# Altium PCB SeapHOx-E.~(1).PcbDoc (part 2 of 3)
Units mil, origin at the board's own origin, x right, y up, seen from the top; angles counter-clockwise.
Board outline 7300 x 3625 mil, 4 copper layers (Top Layer, Internal Plane 1, Signal Layer 1, Bottom Layer), stack 30.634 mil thick; 244 components, 217 nets, 966 pads, 416 vias.
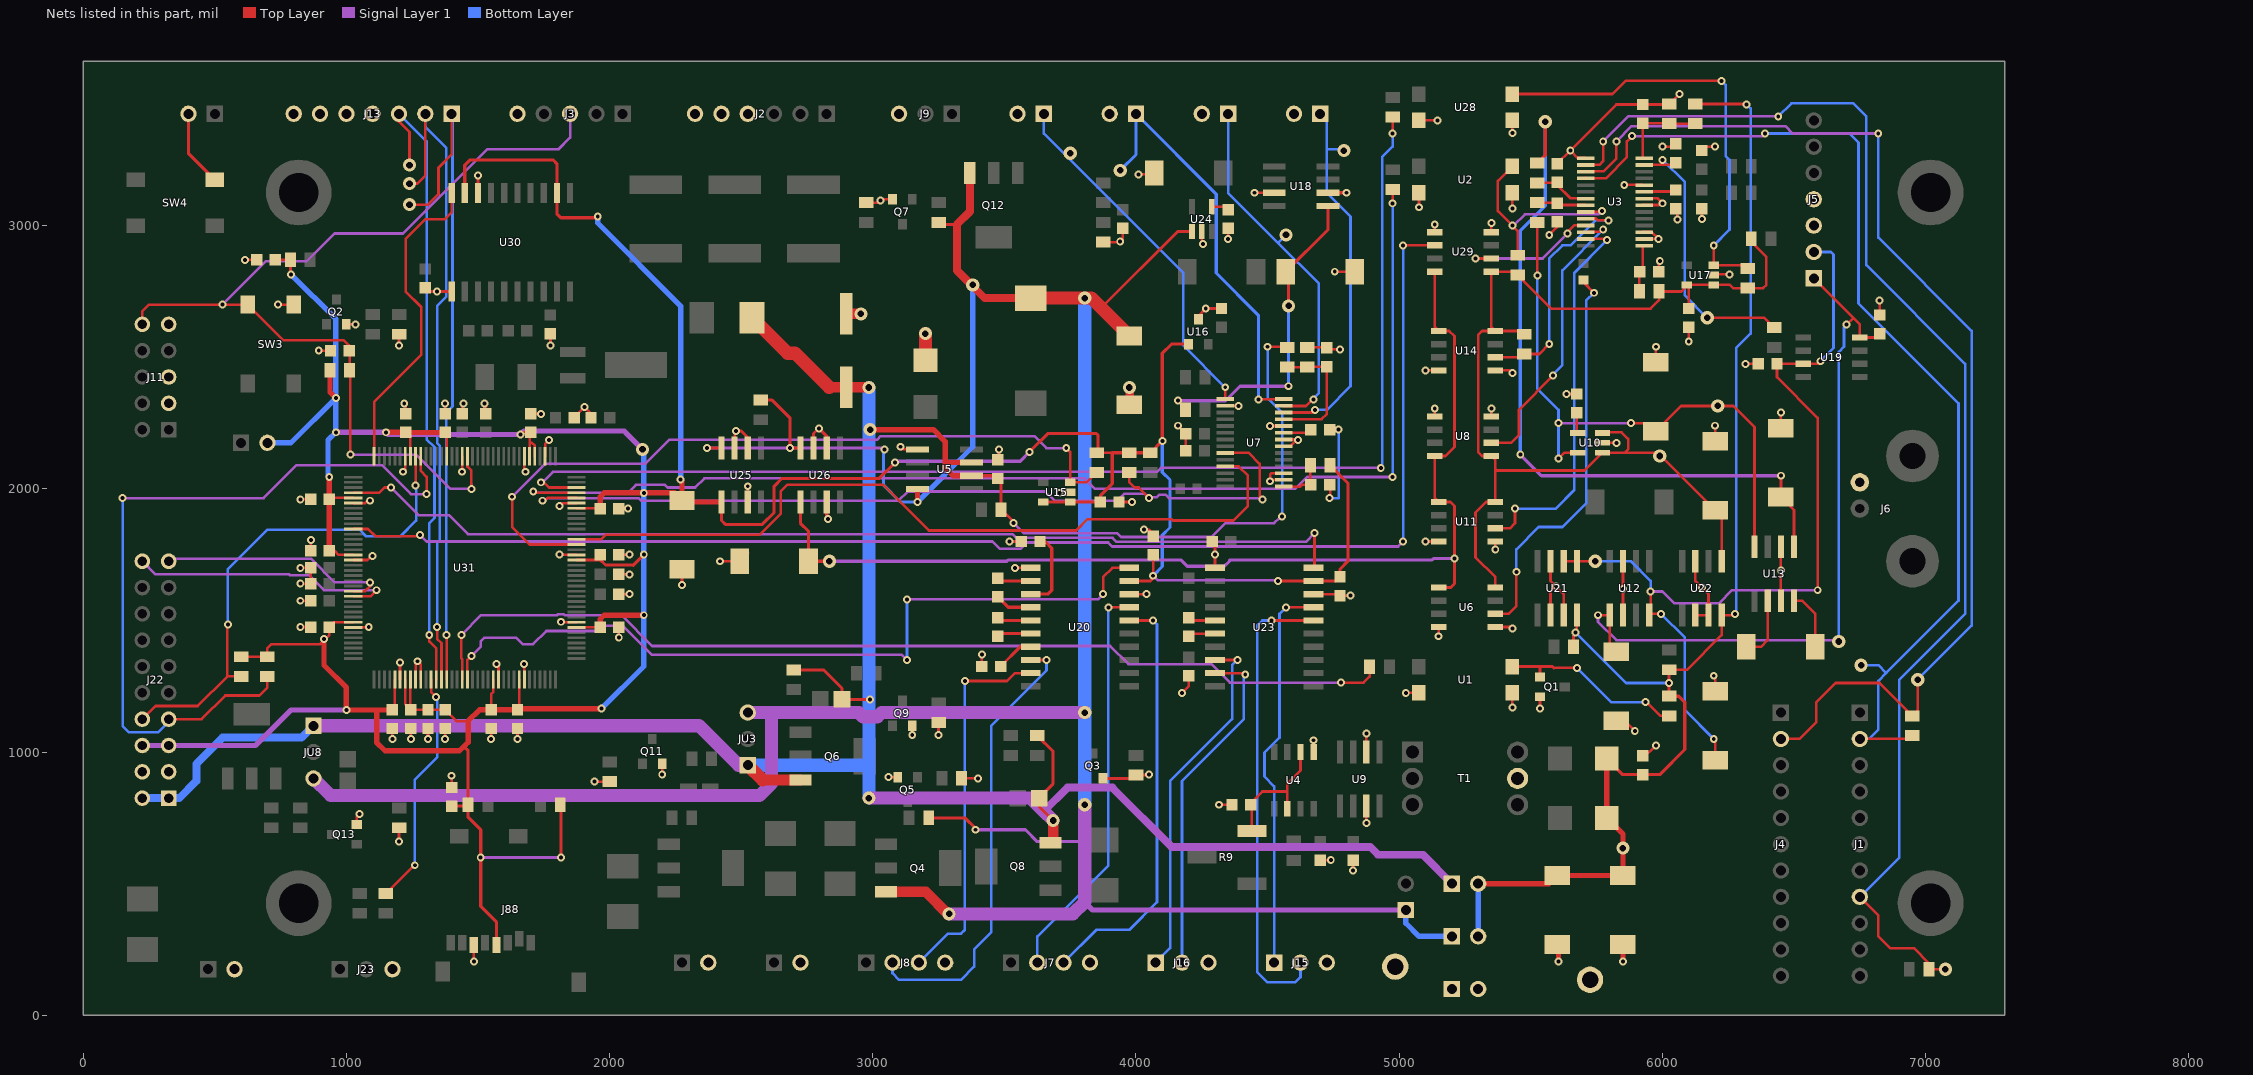
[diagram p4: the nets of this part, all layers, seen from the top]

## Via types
v1: diameter 30, hole 15, Top Layer to Bottom Layer, 378 vias
v2: diameter 50, hole 25, Top Layer to Bottom Layer, 38 vias

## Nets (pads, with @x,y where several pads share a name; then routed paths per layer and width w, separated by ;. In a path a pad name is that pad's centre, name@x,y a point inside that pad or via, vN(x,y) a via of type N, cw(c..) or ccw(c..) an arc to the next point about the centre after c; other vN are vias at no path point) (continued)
+3.3V: C7.1 C8.1 C9.1 C14.1 C22.1 C24.1 C44.2 C45.1 C50.2 C51.1 C74.2 C75.2 C76.2 C102.1 C112.1 C113.1 C114.2 C115.1 C116.1 C117.1 C118.1 J22.5 J22.6 J88.4 JU7.2 R45.2 R46.2 R47.2 R48.2 R49.2 R51.2 R57.1 R58.2 R62.2 R63.2 U15.1 U15.5 U16.1 U20.19 U23.19 U25.1 U30.12 U30.19 U31.5 U31.7 U31.8 U31.24 U31.29 U31.43 U31.56 U31.66 U31.77 U31.78 U31.94 U31.101 U31.113 U31.124 U31.137 | length 17978.5
  Top Layer w10: R63.2@600,1362.4 R62.2@700,1362.4 700,1395 715,1410 900,1410 915,1425 935.43,1445.43 C14.1@935.43,1475 953.74,1493.31 U31.137@1025.76,1493.31 ; C102.1@730.43,2870 R57.1@787.6,2870 787.6,2817.4 v1(790,2815) ; C7.1@935.43,1765 955,1765 970.79,1749.21 U31.124@1025.76,1749.21 ; C118.1@941.18,1965.75 U31.113@1025.76,1965.75 ; 1115,1037 1115,1040 ; 1147,1005 1150,1005 ; C74.2@1175,1160.43 1184.25,1169.68 U31.5@1184.25,1275.76 ; U31.7@1223.62,1275.76 1223.62,1181.81 C8.1@1243.31,1162.13 ; C117.1@1225,2214.57 1243.31,2196.26 U31.101@1243.31,2124.24 ; U31.8@1243.31,1275.76 C8.1@1243.31,1162.13 ; C116.1@1375,2214.57 1381.1,2208.46 U31.94@1381.1,2124.24 ; R51.2@1457.16,794.57 1462.6,794.57 R51.2@1462.6,800 ; 1462.6,1117.6 1417.83,1117.6 C9.1@1375,1160.43 C8.1@1245,1160.43 C8.1@1243.31,1162.13 ; C75.2@1550,1160.43 1550,1220 1558.27,1228.27 U31.24@1558.27,1275.76 ; C76.2@1650,1160.43 1650,1167.13 1656.69,1167.13 U31.29@1656.69,1275.76 ; v1(1662,2207) 1669.57,2214.57 C115.1@1700,2214.57 1696.06,2210.63 1696.06,2175 ; U31.78@1696.06,2124.24 1696.06,2175 ; U31.77@1715.75,2124.24 1715.75,2164.25 1705,2175 1696.06,2175 ; U31.43@1874.24,1473.62 1963.19,1473.62 C112.1@1964.57,1475 ; U31.56@1874.24,1729.53 1950,1730 1964.57,1730 1964.57,1730.43 C113.1@1964.57,1750 ; U31.66@1874.24,1926.38 1963.19,1926.38 C114.2@1964.57,1925 ; C45.1@2275,1955.91 2278,1955.91 2278,1950 C45.1@2280.91,1950 ; R49.2@3850,2137.4 3910,2137.4 3910,2135 ; U20.19@3974.02,1650 4055,1650 4065,1660 v1(4065,1670) C22.1@4065,1749.57 ; v1(4539,1650) U23.19@4674.02,1650 4759.57,1650 C51.1@4775,1665.43
  Top Layer w12: C44.2@1400,794.57 R51.2@1457.16,794.57 ; 1446.3,1021.3 1462.6,1005 R51.2@1462.6,800 1462.6,752.4 1510.43,704.57 v1(1510.43,600) 1510.43,414.57 1570.08,354.92 J88.4@1570.08,267.13 ; U30.19@1450,3124.02 1450,3230 1470,3250 1785,3250 1800,3235 U30.12@1800,3124.02 1800,3045 1815,3030 1950,3030 v1(1955,3035) ; R45.2@1812.4,800 1815,797.4 v1(1815,600) ; C113.1@1964.57,1730.43 1984.35,1710.65 2090,1710.65 ; 2090,1710 v1(2130,1750) ; U25.1@2425,1950 2425,1880 2440,1865 2580,1865 2625,1910 2625,2010 2655,2040 3025,2040 v1(3085,2100) ; v1(3595,2140) 3665,2210 3850,2210 3855,2205 R49.2@3855,2142.4 ; U15.5@3647.64,1950 C50.2@3864.57,1950 3864.57,1974.57 3910,2020 3910,2135 ; 3910,2137.4 R48.2@3975,2137.4 R47.2@4055,2137.4 v1(4100,2182.4) 4100,2515 4135,2550 U16.1@4200,2550 ; R46.2@4737.4,2090 4805,2022.4 4805,1725 4775,1695 C51.1@4775,1665.43
  Top Layer w20: v1(915,1430) 915,1425 915,1330 1000,1245 v1(1000,1160) 1174.57,1160 C74.2@1175,1160.43 ; C118.1@935,1960.43 v1(935,2045) ; C7.1@935.43,1765 C118.1@935.43,1960 ; R58.2@937.6,2450 937.6,2367.4 v1(960,2345) ; 1115,1037 1147,1005 ; 1115,1040 1115,1150 ; 1150,1005 1430,1005 1446.3,1021.3 1462.6,1037.6 1462.6,1117.6 1505.43,1160.43 C75.2@1550,1160.43 C76.2@1650,1160.43 1654.57,1165 v1(1970,1165) ; v1(1150,2215) 1224.57,2215 C117.1@1225,2214.57 C116.1@1375,2214.57 ; C112.1@1964.57,1475 1964.57,1504.57 1980,1520 v1(2130,1520) ; C114.2@1964.57,1925 1964.57,1969.57 1980,1985 v1(2130,1985) 2245.91,1985 C45.1@2275,1955.91 2275,2030 v1(2270,2035) ; C45.1@2280.91,1950 U25.1@2425,1950
  Signal Layer 1 w10: v1(935,2045) v1@937.5,2042.5 ; v1(4065,1670) 4082,1653 4536,1653 v1(4539,1650)
  Signal Layer 1 w12: v1(1510.43,600) v1(1815,600) ; v1(3085,2100) 3075,2100 3080,2105 3560,2105 v1(3595,2140)
  Signal Layer 1 w20: J22.6@225,1025 J22.5@325,1025 655,1025 790,1160 v1(1000,1160) ; v1(960,2215) v1(1150,2215) 1158,2207 v1(1662,2207) 1675,2220 2055.43,2220 ; 2060.43,2214.57 2065,2210 v2(2125,2150)
  Bottom Layer w12: v1(4065,1670) 4100,1705 4100,1824.35 4129,1853.35 4129,2034.05 4100,2063.05 v1(4100,2182.4)
  Bottom Layer w20: JU7.2@700,2175 790,2175 v1(960,2345) ; v1(790,2815) 960,2645 v1(960,2345) ; v1(935,2045) 930,2050 930,2185 v1(960,2215) v1(960,2345) ; v1(1955,3035) 1955,3010 2270,2695 v1(2270,2035) ; v1(1970,1165) 2130,1325 v1(2130,1520) v1(2130,1750) v1(2130,1985) 2130,2145 v2(2125,2150)
+3.3V_OPTOISOLATOR: C65.1 U6.1 U8.8 U11.1 U14.1 U26.1 U29.8 | length 4136.5
  Top Layer w10: U29.8@5135,2825 5135,2615 U14.1@5150,2600 5190,2600 5210,2580 5210,2160 5175,2125 U8.8@5135,2125 5135,1965 U11.1@5150,1950
  Top Layer w12: U26.1@2725,1950 2725,1870 2755.91,1839.09 C65.1@2755.91,1725 v2(2835,1725) ; U6.1@5150,1625 5195,1625 5210,1640 v1(5210,1735) 5210,1935 5195,1950 U11.1@5150,1950
  Signal Layer 1 w12: v2(2835,1725) 3510,1725 3515,1730 4170,1730 4194,1706 4336,1706 4355,1725 4355,1730 5125,1730 5130,1735 v1(5210,1735)
+5V: C6.1 JU1.1 JU2.1 JU3.3 JU8.3 L1.2 Q4.3 Q12.3 R11.2 R22.2 R26.2 U5.8 U24.1 U25.8 U26.8 | length 12528.4
  Top Layer w10: R26.2@3250,3012.6 3257.6,3012.6 R26.2@3257.6,3005
  Top Layer w12: v1(2370,2155) 2370.28,2154.72 U25.8@2425,2154.72 ; R11.2@2575,2337.4 2617.6,2337.4 2685,2270 v1(2685,2155) 2724.72,2155 U26.8@2725,2154.72 ; R22.2@3212.4,750 3350,750 3390,710 v1(3390,705) ; R26.2@3257.6,3005 3320,3005 ; 3870.91,2690.91 4158,2978 U24.1@4212.6,2978
  Top Layer w20: v1(3170,1950) 3170.28,1950.28 U5.8@3170.28,2000
  Top Layer w30: Q12.3@3368.9,3200 3368.9,3053.9 3320,3005 3320,2830 3425.39,2724.61 L1.2@3600,2724.61
  Top Layer w40: Q4.3@3050,468.9 3201.1,468.9 v2@3287.5,382.5
  Top Layer w50: L1.2@3600,2724.61 v2(3805,2724.61) 3831.3,2724.61 3867.95,2687.95 C6.1@3975,2580.91
  Signal Layer 1 w12: v1(2370,2155) v1(2685,2155) 3040,2155 v1(3045,2150) ; v1(3390,705) 3580,705 3625,660 3805,660
  Signal Layer 1 w20: 3805,430 3835,400 JU2.1@5025,400
  Signal Layer 1 w50: JU8.3@875,900 940,835 2570,835 2615,880 2615,1150 ; JU3.3@2525,1150 2615,1150 ; v2(3290,385) 3760,385 3805,430 3805,660 v2(3805,800) ; v2(3805,1150) 3033.34,1150 3017.34,1134 2962.66,1134 2946.66,1150 2615,1150
  Bottom Layer w12: v1(3045,2150) 3041,2146 3041,2014 3105,1950 v1(3170,1950)
  Bottom Layer w20: v1(3170,1950) 3380,2160 v2(3380,2775) ; JU2.1@5025,400 5025,350 5075,300 JU1.1@5200,300
  Bottom Layer w50: v2(3805,800) v2(3805,1150) v2(3805,2724.61)
-2.5V: C63.2 R33.2 U18.5 | length 1305.3
  Top Layer w12: v1(4160,2335) 4187.6,2307.4 R33.2@4187.6,2300 ; v2(4580,2695) 4580,2814.09 C63.2@4569.09,2825 4729.72,2985.63 U18.5@4729.72,3075
  Signal Layer 1 w12: v1(4160,2335) 4340,2335 4395,2390 v1(4580,2390)
  Bottom Layer w12: v1(4580,2390) 4580,2725 v2(4580,2695)
ADS1248_NI_AIN3: J14.1 U7.12 | length 1438
  Top Layer w10: U7.12@4561,2290.16 4670.16,2290.16 v1(4680,2300)
  Bottom Layer w10: v1(4680,2300) 4725,2300 4815,2390 4815,3035 4725,3125 4725,3290 ; J14.1@4700,3425 4725,3400 4725,3290 ; v2@4785,3290 4725,3290
  other v2: 4790,3285
ADS1248_NI_AIN4: J17.1 U7.13 | length 1410.3
  Top Layer w10: U7.13@4561,2315.75 4561.75,2315 4645,2315 4670,2340 v1(4675,2340)
  Bottom Layer w10: J17.1@4350,3425 4350,3125 4540,2935 ; v2(4570,2965) 4540,2935 ; v1(4675,2340) 4670,2340 4695,2365 4695,2780 4540,2935
ADS1248_NI_AIN5: J19.1 U7.14 | length 1614
  Top Layer w10: v1(4465,2340) 4559.66,2340 U7.14@4561,2341.34
  Bottom Layer w12: v2(3940,3210) 4000,3270 J19.1@4000,3425 4305,3120 4305,2820 4465,2660 v1(4465,2340)
ADS1248_NI_AIN6: J18.1 U7.15 | length 1369.1
  Top Layer w10: U7.15@4339,2341.34 v1(4339,2386)
  Bottom Layer w10: J18.1@3650,3425 3650,3350 4180,2820 4180,2545 v1(4339,2386)
  other v2: 3750,3275
ADS1248ISO_DRDY: U29.6 U31.119 | length 5293.7
  Top Layer w10: U31.119@1025.76,1847.64 1082.36,1847.64 1110,1820 1275,1820 v1(1280,1825) ; v1(5015,2925) U29.6@5135,2925
  Signal Layer 1 w10: v1(1280,1825) 1305,1800 3455,1800 3483,1772 3561,1772 3585,1796 3894,1796 3909,1781 4996,1781 v1(5015,1800)
  Bottom Layer w10: v1(5015,1800) v1(5015,2925)
ADS1248ISO_PWR_ON: R1.1 U31.18 | length 3808.3
  Top Layer w10: v1(1437,1445) 1437,1356.16 1440.16,1353 U31.18@1440.16,1275.76 ; v1(4779,1264) 4864.6,1264 4887.6,1287 R1.1@4887.6,1325
  Signal Layer 1 w10: v1(1437,1445) 1512,1520 1800.4,1520 1803.4,1523 1826.6,1523 1829.6,1520 2045,1520 2162,1403 3902,1403 3971,1334 4287,1334 4357,1264 v1(4779,1264)
ADS1248ISO_RESET: R59.1 U31.70 | length 4706.5
  Top Layer w10: v1(1740,2025) 1750.24,2025 1770.12,2005.12 U31.70@1874.24,2005.12 ; v1(4975,3350) R59.1@4975,3412.6
  Signal Layer 1 w10: v1(1740,2025) 1745,2025 1785,2065 4080,2065 4095,2080 4518,2080 v1(4930,2080)
  Bottom Layer w10: v1(4930,2080) 4935,2085 4935,3260 4975,3300 v1(4975,3350)
ADS1248ISO_START: R56.1 U31.69 | length 4578.3
  Top Layer w10: v1@1715,1985 1785,1985 1785.43,1985.43 U31.69@1874.24,1985.43 ; v1(4975,3085) R56.1@4975,3137.6
  Signal Layer 1 w10: v1@1715,1985 2070,1985 2100,2015 2210,2015 2220,2005 2325.46,2005 2360.46,2040 3805,2040 3845,2000 4605,2000 4650,2045 v1(4975,2045)
  Bottom Layer w10: v1(4975,2045) v1(4975,3085)
  other v1: 1710,1990
ADS1248NONISO_DRDY: U7.25 U31.60 | length 3016.2
  Top Layer w10: U31.60@1874.24,1808.27 1968.27,1808.27 1985,1825 2570,1825 2650,1905 2650,1990 2675,2015 3040,2015 3213,1842 3773,1842 3816,1885 4135,1885 4140,1880 4370,1880 4425,1935 4425,2050 4389.57,2085.43 U7.25@4339,2085.43
ADS1248NONISO_RESET: R49.1 U15.3 U31.59 | length 2857.7
  Top Layer w10: v1(1630,1970) 1630,1855 1696.42,1788.58 U31.59@1874.24,1788.58 ; v1(3735,2155) 3750,2140 U15.3@3750,2024.8 3812.2,2024.8 R49.1@3850,2062.6
  Signal Layer 1 w10: v1(1630,1970) 1755,2095 2135,2095 2227,2187 3017,2187 3030,2200 3615,2200 3660,2155 v1(3735,2155)
ADS1248NONISO_START: R48.1 U7.23 U31.68 | length 3362.1
  Top Layer w10: v1(1745,1955) 1755,1955 1765.75,1965.75 U31.68@1874.24,1965.75 ; R48.1@3975,2062.6 3975,2024.65 3994.66,2005 4010,2005 v1(4050,1965) ; U7.23@4339,2136.61 4428.39,2136.61 4470,2095 4470,1970 v1(4480,1960)
  Signal Layer 1 w10: v1(1745,1955) 1755,1955 1765,1965 2110,1965 2120,1955 3098,1955 3133,1990 3655,1990 3690,1955 3930,1955 3957,1982 4033,1982 v1(4050,1965) 4053,1968 4078.4,1968 4088.4,1978 4111.6,1978 4124.6,1965 4475,1965 v1(4480,1960)
"AIN0 OR GPIO0": J13.1 U31.15 | length 2614.5
  Top Layer w10: v2(1240,3080) 1310,3080 1350,3120 1350,3220 1400,3270 J13.1@1400,3425 ; v1(1380,1445) 1381.1,1443.9 U31.15@1381.1,1275.76
  Bottom Layer w10: v1(1380,1445) 1380,2290.4 1403,2313.4 1403,3425 J13.1@1400,3425
"AIN1 OR GPIO1": J13.2 U31.14 | length 2519.4
  Top Layer w10: v2(1240,3160) 1270,3160 1300,3190 J13.2@1300,3425 ; v1(1345,1475) 1345,1430 1361.42,1413.58 U31.14@1361.42,1275.76
  Bottom Layer w10: J13.2@1300,3425 1300,3375 1380,3295 1380,2730 1345,2695 1345,2173.75 1355,2163.75 1355,1805 1345,1795 v1(1345,1475)
"AIN2 OR GPIO2": J13.3 U31.13 | length 2436.1
  Top Layer w10: J13.3@1200,3425 1200,3395 1240,3355 v2(1240,3230) ; v1(1315,1445) 1315,1420 1341.73,1393.27 U31.13@1341.73,1275.76
  Bottom Layer w10: J13.3@1200,3425 1305,3320 1305,2188.29 1335,2158.29 1335,1890 1315,1870 v1(1315,1445)
ARM_RESET: C61.2 J3.3 J11.10 R58.1 SW3.2 U31.90 | length 3664
  Top Layer w10: J11.10@225,2625 225,2675 250,2700 v1(530,2700) SW3.2@625,2700 760,2565 990,2565 1010.43,2544.57 C61.2@1010.43,2525 1012.4,2523.03 R58.1@1012.4,2450 1015,2447.4 v1(1015,2130) ; U31.90@1459.84,2124.24 1459.84,2084.76 1475,2069.6 v1(1475,2000)
  Signal Layer 1 w10: v1(530,2700) 695,2865 850,2865 955,2970 1215,2970 1535,3290 1805,3290 1850,3335 J3.3@1850,3425 ; v1(1015,2130) 1265,2130 1395,2000 v1(1475,2000) 1475,2020
AUX_REF: C46.2 R21.2 U3.13 | length 1099.1
  Top Layer w10: U3.13@5925,3232.09 5995,3232.09 ; v1(6000,3250) 5995,3255 5995,3232.09 ; C46.2@6050,3239.57 6042.52,3232.09 5995,3232.09 ; v2(6170,2650) 6387.4,2650 R21.2@6425,2612.4
  Bottom Layer w10: v1(6000,3250) 6085,3165 6085,2735 v2(6170,2650)
BATT_VOLT: C11.2 R13.2 R14.1 U7.11 | length 502.8
  Top Layer w10: U7.11@4561,2264.57 4704.57,2264.57 4725,2285 C11.2@4725,2464.57 4651.97,2464.57 R13.2@4650,2462.6 R14.1@4575,2462.6
BATTERY: C4.1 C5.2 D9.2 D10.2 FS1.2 J22.1 J22.2 JU3.1 JU4.1 JU8.1 Q6.3 Q8.3 R8.1 R14.2 R19.2 R29.2 U5.2 U5.3 | length 11668
  Top Layer w10: v2(2990,2225) 3210,2225 ; 3280,2100 3280,2155 ; R8.1@3487.4,1920 3490,1920 3540,1870 v1(3535,1870) ; R19.2@3610,1069 3610,1062.4 R19.2@3625,1062.4 ; Q8.3@3675,656.1 3685,656.1 Q8.3@3685,666.1 ; v1(4500,2540) 4572.4,2540 R14.2@4575,2537.4
  Top Layer w12: R29.2@2700,1312.4 2812.6,1312.4 2883,1242 D9.2@2883,1200 v1(2990,1200) ; v2@2984.76,2385.24 v2(2985,2385) ; U5.2@3375,2050 3464.57,2050 C5.2@3475,2039.57 3487.4,2027.17 R8.1@3487.4,1920 ; R19.2@3625,1062.4 3685,1002.4 3685,880 3633,828 3633,792 v2(3685,740)
  Top Layer w20: v2(2990,2225) 3230,2225 3275,2180 3275,2080 3305,2050 U5.2@3375,2050 ; 3280,2100 U5.3@3375,2100
  Top Layer w40: 2581.1,893.9 Q6.3@2725,893.9 ; 2834.76,2385.24 C4.1@2900,2385.24 v2@2984.76,2385.24 ; Q8.3@3685,666.1 v2(3685,740)
  Top Layer w50: JU3.1@2525,950 2581.1,893.9 ; FS1.2@2541.34,2650 2676.34,2515 2705,2515 2834.76,2385.24
  Signal Layer 1 w10: v1(3535,1870) 3573,1832 3928,1832 3943,1817 4287,1817 4340,1870 4525,1870 4545,1890 4555,1890 v1(4555,1895)
  Signal Layer 1 w30: 3650,775 3740,865 3910,865 4135,640 4890,640 4920,610 5090,610 JU4.1@5200,500
  Signal Layer 1 w50: JU8.1@875,1100 2340,1100 2490,950 JU3.1@2525,950 ; v2(2985,825) 3600,825 3650,775 v2(3685,740)
  Bottom Layer w10: v1(4500,2540) 4500,2345 4555,2290 v1(4555,1895)
  Bottom Layer w30: J22.2@225,825 J22.1@325,825 365,825 430,890 430,955 530,1055 830,1055 JU8.1@875,1100
  Bottom Layer w50: JU3.1@2525,950 2980,950 2985,955 ; v2(2985,825) 2985,955 ; v2(2985,2385) 2985,955
COM1_ON: U20.20 U31.19 | length 3046.2
  Top Layer w10: U31.19@1459.84,1275.76 1459.84,1349.84 v1(1475,1365) ; v1(3875,1600) 3875,1665 3910,1700 U20.20@3974.02,1700
  Signal Layer 1 w10: v1(1475,1365) 1510,1400 1510,1420 1525,1435 1645,1435 1670,1410 1710,1410 1760,1460 1955,1460 1975,1480 2050,1480 2160,1370 3110,1370 v1(3130,1350) ; v1(3130,1580) 3855,1580 v1(3875,1600)
  Bottom Layer w10: v1(3130,1350) v1(3130,1580)
COM2_ON: U23.20 U31.112 | length 3893.8
  Top Layer w10: U31.112@1025.76,1985.43 1125.43,1985.43 1145,2005 v1(1170,2005) ; U23.20@4674.02,1700 4678,1703.98 v1(4678,1832)
  Signal Layer 1 w10: v1(1170,2005) 1275,1900 1390,1900 1462,1828 1962.4,1828 1963.4,1827 1986.6,1827 1987.6,1828 3531.6,1828 3545.6,1814 3911,1814 3926,1799 4645,1799 v1(4678,1832)
CONSOLE_ON: U30.20 U31.108 | length 1215.4
  Top Layer w10: U31.108@1105.51,2124.24 1105.51,2330.51 1285,2510 1285,2690 1225,2750 1225,2950 1300,3025 1375,3025 1400,3050 U30.20@1400,3124.02
DATA_FROM_AUX1: J15.2 U23.16 | length 1782.2
  Top Layer w10: v1(4515,1500) U23.16@4674.02,1500
  Bottom Layer w10: v1(4515,1500) 4480,1500 4460,1480 4460,165 4500,125 4605,125 4625,145 J15.2@4625,200
DATA_FROM_AUX2: J16.2 U23.9 | length 1321.5
  Top Layer w10: U23.9@4300,1300 4410,1300 v1(4415,1295)
  Bottom Layer w10: J16.2@4175,200 4175,890 4410,1125 4410,1300 v1(4415,1295)
DATA_FROM_MICROCAT: J7.3 U20.16 | length 1617.5
  Top Layer w10: U20.16@3974.02,1500 v1(4065,1500)
  Bottom Layer w10: J7.3@3725,200 3850,325 3975,325 4080,430 4080,1485 v1(4065,1500)
DATA_FROM_OPTODE: J8.3 U20.9 | length 1434.2
  Top Layer w10: v1(3350,1270) 3510,1270 3540,1300 U20.9@3600,1300
  Bottom Layer w10: J8.3@3175,200 3285,310 3335,310 3350,325 v1(3350,1270)
DATA_TO_AUX1: J15.1 U23.17 | length 1505.4
  Top Layer w10: v1@4570,1545 4572.5,1547.5 4575,1550 U23.17@4674.02,1550
  Bottom Layer w10: J15.1@4525,200 4525,870 4488,907 4488,998 4545,1055 4545,1525 v1(4570,1550)
DATA_TO_AUX2: J16.1 U23.8 | length 1363.4
  Top Layer w10: U23.8@4300,1350 v1(4385,1350)
  Bottom Layer w10: J16.1@4075,200 4130,255 4130,890 4365,1125 4365,1330 v1(4385,1350)
DATA_TO_MICROCAT: J7.2 U20.17 | length 1540.9
  Top Layer w10: v1(3895,1550) U20.17@3974.02,1550
  Bottom Layer w10: J7.2@3625,200 3625,300 3895,570 v1(3895,1550)
DATA_TO_OPTODE: J8.2 U20.8 | length 1720
  Top Layer w10: U20.8@3600,1350 v1(3660,1350)
  Bottom Layer w10: J8.2@3075,200 3075,160 3100,135 3335,135 3385,185 3385,250 3450,315 3450,1100 3660,1310 v1(3660,1350)
GND: C2.1 C3.2 C4.2 C5.1 C6.2 C7.2 C8.2 C9.2 C10.2 C11.1 C13.1 C14.2 C15.1 C17.2 C18.2 C22.2 C24.2 C25.2 C28.2 C36.1 C43.2 C44.1 C45.2 C50.1 C51.2 C52.2 C53.1 C54.2 C55.2 C56.2 C60.1 C61.1 C63.1 C64.2 C65.2 C74.1 C75.1 C76.1 C101.2 C102.2 C105.2 C112.2 C113.2 C114.1 C115.2 C116.2 C117.2 C118.2 C120.2 C121.2 C122.2 C123.2 C124.2 C125.2 D8.1 J2.4 J2.5 J2.6 J3.5 J7.4 J8.4 J9.3 J10.2 J11.3 J11.5 J11.9 J12.2 J13.4 J13.5 J13.6 J13.7 J14.2 J15.3 J16.3 J17.2 J18.2 J19.2 J20.2 J21.2 J22.3 J22.4 J23.3 J88.6 JU5.1 Q2.2 Q3.2 Q5.2 Q7.2 Q9.2 Q11.2 Q13.2 R13.1 R20.1 R25.1 R28.1 R30.1 R32.1 R35.2 R44.1 R54.1 SW3.4 SW4.2 TP2.1 U1.2 U2.2 U4.1 U5.5 U6.4 U7.2 U7.3 U7.7 U7.8 U7.10 U7.16 U8.5 U9.2 U9.7 U11.4 U14.4 U15.2 U16.3 U18.3 U18.6 U20.1 U20.18 U23.1 U23.18 U24.2 U25.3 U25.6 U25.7 U26.3 U26.6 U26.7 U28.2 U29.5 U30.1 U30.18 U31.6 U31.9 U31.10 U31.25 U31.30 U31.44 U31.57 U31.67 U31.75 U31.79 U31.91 U31.102 U31.114 U31.125 U31.138 | length 7974.4
  Top Layer w10: v1(615,2870) C102.2@659.57,2870 ; v1(740,2700) SW3.4@800,2700 ; v1(825,1475) C14.2@864.57,1475 ; v1(825,1575) C54.2@864.57,1575 ; v1(825,1640) C55.2@849.57,1640 ; v1(825,1700) C120.2@864.57,1700 ; v1(825,1960) C118.2@864.57,1960 ; C55.2@864.57,1625 C55.2@849.57,1640 ; v1(865,1805) 864.57,1804.57 C7.2@864.57,1765 C7.2@875,1754.57 ; C120.2@875,1710.43 C120.2@864.57,1700 ; v1@890,2525 v1(895,2525) C61.1@939.57,2525 ; Q2.2@999.8,2625 v1(1035,2625) ; U31.138@1025.76,1473.62 v1@1083.62,1473.62 ; U31.125@1025.76,1729.53 1079.53,1729.53 v1@1097.5,1747.5 ; U31.114@1025.76,1946.06 1071.06,1946.06 v1@1085,1960 ; Q13.2@1040,724.8 1040,755 v1(1050,765) ; v1@1085,1473.62 v1@1083.62,1473.62 ; v1(1085,1475) v1@1083.62,1473.62 ; v1(1175,1050) C74.1@1175,1089.57 ; R44.1@1187.4,700 1187.4,712.6 R44.1@1200,712.6 ; v1(1200,2545) R54.1@1200,2587.6 ; 1203.94,1322.26 U31.6@1203.94,1275.76 v1(1203.94,1341.06) ; v1@1203.94,1339.94 v1(1203.94,1341.06) ; v1@1203.94,1350 v1(1203.94,1341.06) ; v1@1220,2065 1223.62,2068.62 U31.102@1223.62,2124.24 ; v1(1220,2325) 1225,2320 C117.2@1225,2285.43 ; v1(1245,1050) C8.2@1245,1089.57 ; U31.9@1262.99,1275.76 1262.99,1337.99 v1(1270,1345) 1282.68,1332.32 U31.10@1282.68,1275.76 ; v1(1310,1050) C24.2@1310,1089.57 ; v1(1375,1050) C9.2@1375,1089.57 ; C116.2@1375,2285.43 v1(1375,2325) ; C44.1@1400,865.43 v1@1400,900 ; v1(1440,2065) 1440.16,2065.16 U31.91@1440.16,2124.24 ; C124.2@1440,2285.43 1440,2320 v1(1445,2325) ; J88.6@1483.46,267.13 1483.46,206.53 v1(1485,205) ; C123.2@1525,2285.43 v1(1525,2325) ; C123.2@1530,2285.43 v1@1530,2322 ; v1(1550,1050) C75.1@1550,1089.57 ; v1(1570,1335) 1577.95,1327.05 U31.25@1577.95,1275.76 ; v1(1650,1050) C76.1@1650,1089.57 ; v1(1675,1335) 1665,1335 v1@1676.38,1323.62 ; U31.30@1676.38,1275.76 v1@1676.38,1323.62 ; v1@1676.38,1335 v1@1676.38,1323.62 ; U31.79@1676.38,2124.24 1676.38,2068.62 v1(1680,2065) ; C115.2@1700,2285.43 1739.57,2285.43 v1(1740,2285) ; U31.75@1755.12,2124.24 1755.12,2169.88 v1@1775,2189.76 ; v1(1810,1750) 1810.79,1749.21 U31.57@1874.24,1749.21 ; v1(1810,1935) 1821.06,1946.06 U31.67@1874.24,1946.06 ; v1(1815,1495) 1816.69,1493.31 U31.44@1874.24,1493.31 ; C125.2@1865.43,2270 1865.43,2270.86 v1(1905,2310.43) 1929.57,2285.86 C122.2@1929.57,2270 ; v1(1942.4,887.6) R32.1@2000,887.6 ; v1(2035,1435) 2035.43,1435.43 C112.2@2035.43,1475 ; C121.2@2035.43,1600 v1(2075,1600) ; C56.2@2035.43,1675 v1(2075,1675) ; C113.2@2035.43,1750 v1(2075,1750) ; C114.1@2035.43,1925 v1(2070,1925) ; Q11.2@2199.8,955 2199.8,915.2 v1(2200,915) ; v1(2420,1725) C65.2@2494.09,1725 C65.2@2494.09,1712 ; U25.7@2475,2154.72 2475,2215 v1@2475,2220 ; U25.3@2525,1950 v1(2525,2010) ; U26.7@2775,2154.72 2775,2210 v1(2795,2230) ; R28.1@2975,3087.4 3022.4,3087.4 v1(3030,3095) 3025,3100 Q7.2@3075.2,3100 ; v1(3060,905) Q5.2@3095.2,905 ; v1(3105,2160) 3105,2150 U5.5@3170.28,2150 ; Q9.2@3149.8,1100 3149.8,1065.2 v1(3150,1065) ; D8.1@3200,2488.58 D8.1@3223.42,2512 ; R25.1@3337.4,900 v1(3400,900) ; C18.2@3414.57,1325 v1@3414.57,1369.57 ; C5.1@3475,2110.43 C5.1@3480,2115.43 ; v1(3540,1700) U20.1@3600,1700 ; C17.2@3564.57,1800 C17.2@3569,1795.57 ; v1@3712.4,1987.4 U15.2@3750,1987.4 ; Q3.2@3874.8,900 3910,900 ; R35.2@3875,2937.6 3937.6,2937.6 v1(3940,2940) 3950,2950 C15.1@3950,2989.57 ; U20.18@3974.02,1600 v1(4040,1600) ; C6.2@3975,2290 C6.2@3975,2319.09 3987,2319.09 v2@3987,2395 ; v1(4010,3195) 4064.09,3195 C64.2@4069.09,3200 C64.2@4069.09,3198 ; v1(4030,1845) 4050,1845 4065,1830 C22.2@4065,1820.43 ; v1(4160,2240) 4189.57,2210.43 C53.1@4189.57,2210 C60.1@4189.57,2145 ; v1(4175,1225) 4200,1250 C43.2@4200,1289.57 ; U16.3@4237.4,2644.49 4237.4,2657.4 v1(4265,2685) ; U24.2@4250,2978 4250,2935 v1(4255,2930) ; v1@4265.43,2685.43 C10.2@4325,2685.43 ; C52.2@4289.57,1800 4300,1789.57 v1(4300,1750) U23.1@4300,1700 ; v1(4315,800) C3.2@4364.57,800 ; U7.16@4339,2315.75 4389.25,2315.75 v1(4390,2315) ; v1(4350,2950) C13.1@4350,2989.57 ; v1(4450,3125) U18.3@4525,3125 ; v1(4508.81,2029) 4508.81,2033.81 v1@4510,2035 ; v1(4508.98,2238.98) U7.10@4561,2238.98 v1@4523,2238.98 ; v1@4510,2039 v1@4510,2035 ; U7.2@4561,2034.25 v1@4510.75,2034.25 ; U7.3@4561,2059.84 4514.84,2059.84 4510,2055 v1@4510,2035 ; U7.7@4561,2162.2 4586.61,2162.2 4612.2,2187.79 U7.8@4561,2187.79 ; R13.1@4650,2537.4 C11.1@4723.03,2537.4 ; U23.18@4674.02,1600 C51.2@4769.57,1600 ; U4.1@4675,1000 v1(4675,1045) ; C36.1@4700,589.57 4739.57,589.57 v1(4740,590) ; v1@4728.4,1966 v1@4737.4,1975 ; C11.1@4729.4,2533 4725,2537.4 C11.1@4723.03,2537.4 ; v1(4735,1965) 4737.4,1967.4 v1@4737.4,1975 ; C2.1@4735.43,2225 v1(4770,2225) ; C28.2@4737.4,2015 v1@4737.4,1975 ; v1(4755,2825) C63.1@4830.91,2825 ; C51.2@4775,1600 C51.2@4769.57,1600 ; v1(4775,2530) 4730.43,2530 C11.1@4725,2535.43 C11.1@4723.03,2537.4 ; v1(4815,1595) 4814.57,1594.57 C51.2@4775,1594.57 C51.2@4769.57,1600 ; C25.2@4824.57,590 C25.2@4825,589.57 ; v1(4875,730) U9.7@4875,795.28 v1@4875,733 ; U9.2@4875,1000 v1(4875,1070) ; v1(5025,1225) U1.2@5065,1225 ; U1.2@5070,1220 U1.2@5075,1225 ; v1(5075,3070) U2.2@5075,3125 ; U28.2@5075,3400 v1(5145,3400) ; v1(5100,1800) U11.4@5150,1800 ; v1(5100,2450) U14.4@5150,2450 ; U8.5@5135,2275 v1(5135,2305) ; U29.5@5135,2975 v1(5135,3005) ; v1(5150,1440) U6.4@5150,1475 ; C55.2@849.57,1640 C55.2@864.57,1640 C120.2@864.57,1700 ; v1@4510,2035 v1@4510.75,2034.25 ; v1@4510,2035 4510,2034.25 v1@4510.75,2034.25
  Top Layer w12: J21.2@400,3425 400,3275 SW4.2@500,3175 ; J23.3@1175,175 J23.3@1180,175 ; v1@1200,665 R44.1@1200,712.6 ; C105.2@1300,2764.57 1314.57,2750 v1(1345,2750) U30.1@1400,2750 ; U30.18@1500,3124.02 v1(1500,3190) ; v1(1775,2545) C101.2@1775,2589.57 ; v1(2275,1635) C45.2@2275,1694.09 ; v1@2475,2215 v1(2480,2220) 2500,2220 2525,2195 U25.6@2525,2154.72 ; C65.2@2494.09,1725 C65.2@2525,1755.91 ; v1(2795,2230) 2825,2200 U26.6@2825,2154.72 ; U26.3@2825,1950 2825,1890 v1(2830,1885) ; v1(3250,1065) R30.1@3250,1112.6 ; v1@3414.57,1369.57 v1(3415,1370) ; C5.1@3480,2115.43 v1(3480,2150) ; v1(3520,1800) C17.2@3564.57,1800 ; v1(3710,1985) v1@3712.4,1987.4 ; Q3.2@3874.8,900 3987.4,900 R20.1@4000,912.6 4047.6,912.6 v1(4050,915) ; C50.1@3935.43,1950 v1(3985,1950) ; U18.6@4729.72,3125 v1(4800,3125) ; v1(4825,550) C25.2@4825,589.57
  Top Layer w30: C6.2@3975,2319.09 v2(3975,2385)
  Top Layer w40: C4.2@2900,2664.76 v2(2954.76,2664.76)
  Top Layer w50: D8.1@3200,2488.58 v2(3200,2590)
  Bottom Layer w10: v1(4735,1965) 4770,1965 v1(4770,2225)
  other v1: 1200,660 1400,910 1100,1745 1090,1955 1215,2065 1770,2185 4615,2185
GREEN-LED: R61.2 U31.12 | length 905
  Top Layer w10: R61.2@1150,462.4 1257.6,570 v1(1260,570) ; U31.12@1322.05,1275.76 1322.05,1227.95 v1(1340,1210)
  Bottom Layer w10: v1(1260,570) 1260,895 1345,980 1345,1205 v1(1340,1210)
I2C0SCL: J22.7 R62.1 U31.99 | length 2950.1
  Top Layer w10: J22.7@325,1125 450,1125 540,1215 670,1215 700,1245 R62.1@700,1287.6 ; U31.99@1282.68,2124.24 1282.68,2068.32 1305,2045.99 v1(1305,1980)
  Signal Layer 1 w10: v1(150,1965) 685,1965 810,2090 1135,2090 1245,1980 v1(1305,1980)
  Bottom Layer w10: v1(150,1965) 150,1100 175,1075 285,1075 325,1115 J22.7@325,1125
I2C0SDA: J22.8 R63.1 U31.100 | length 1911.9
  Top Layer w10: J22.8@225,1125 275,1175 435,1175 547.6,1287.6 ; v1(550,1485) 547.6,1482.6 547.6,1287.6 ; R63.1@600,1287.6 547.6,1287.6 ; v1(1262.5,2012.5) v1@1265,2015 ; v1@1262.99,2015 U31.100@1262.99,2124.24
  Bottom Layer w10: v1(550,1485) 550,1695 700,1845 1050,1845 1075,1820 1205,1820 1265,1880 v1@1265,2012.5 ; v1(1262.5,2012.5) v1@1265,2015
IB+: J1.8 R15.2 U3.16 | length 5014.6
  Top Layer w10: U3.16@5706.5,3232.09 5762.09,3232.09 5775,3245 v1(5775,3320) ; J1.8@6750,450 6820,380 6820,300 6865,255 6955,255 7012.4,197.6 R15.2@7012.4,175 v2(7075,175)
  Signal Layer 1 w10: v1(5775,3320) 5870,3415 v1(6440,3415)
  Bottom Layer w10: v1(6440,3415) 6490,3465 6725,3465 6775,3415 6775,2850 7150,2475 7150,1525 6900,1275 6900,600 J1.8@6750,450
IK+: J1.2 R16.2 U3.18 | length 4075.1
  Top Layer w10: U3.18@5706.5,3180.9 5707.4,3180 5785,3180 5865,3260 5865,3320 v1(5885,3340) ; J1.2@6750,1050 6937.4,1050 6937.4,1059 6946.4,1059 R16.2@6950,1062.6
  Signal Layer 1 w10: v1(5885,3340) 6380,3340 v1(6390,3350)
  Bottom Layer w10: v1(6390,3350) 6710,3350 6745,3315 6745,2705 7125,2325 7125,1575 6850,1300 ; J1.2@6750,1050 6785,1050 6820,1085 6820,1270 6850,1300 ; v2(6755,1330) 6820,1330 6850,1300
IK-: J4.2 R16.1 U3.17 | length 4370.8
  Top Layer w10: U3.17@5706.5,3206.5 5776.5,3206.5 5825,3255 v1(5825,3320) ; J4.2@6450,1050 6520,1050 6585,1115 6585,1190 6657.4,1262.4 6825,1262.4 R16.1@6950,1137.4 6970,1157.4 v2(6970,1275)
  Signal Layer 1 w10: v1(5825,3320) 5883,3378 6467,3378 6495,3350 v1(6820,3350)
  Bottom Layer w10: v1(6820,3350) 6820,2955 7175,2600 7175,1480 v2(6970,1275)
"ISO +2.5V": C47.1 R3.2 U10.5 U13.8 | length 2299.2
  Top Layer w10: v1(5525,2810) R3.2@5525,3012.6 ; v1(5605,2115) 5605,2115.2 5627.4,2137.6 U10.5@5678,2137.6 ; v1(5880,2250) 5944.09,2250 C47.1@5975,2219.09 6070.91,2315 6270,2315 6350,2235 U13.8@6350,1779.72
  Signal Layer 1 w10: v1(5605,2250) v1(5880,2250)
  Bottom Layer w10: v1(5525,2810) 5525,2380 5605,2300 v1(5605,2250) v1(5605,2115)
  other v2: 6210,2315
"ISO +3.3V": C29.1 C30.2 R2.2 R18.2 R40.2 R41.2 R43.1 U6.8 U8.1 U10.1 U10.3 U11.8 U14.8 U17.1 U17.5 U22.1 U29.1 | length 4297.6
  Top Layer w10: U6.8@5365,1625 5365,1665 5290,1740 5290,1910 5330,1950 U11.8@5365,1950 5365,2075 ; R41.2@5475,2587.4 5462.4,2600 U14.8@5365,2600 ; U10.3@5772,2212.4 5774.6,2215 5845,2215 5870,2190 5870,2150 5857.6,2137.6 ; C30.2@6100,2685.43 U17.5@6100,2772.64 ; U22.1@6225,1725 6225,1894.09 C29.1@6200,1919.09 5981.5,2137.6 5857.6,2137.6 ; R43.1@6337.6,2950 6337.6,2937.4 6395,2880 6395,2775 6382.6,2762.6 R40.2@6325,2762.6 6268.4,2762.6 6256,2775 6200,2775 6097.64,2775 6072.64,2750 R2.2@5987.4,2750 5987.4,2717.4 5955,2685 5577.6,2685 R18.2@5450,2812.6 5437.6,2812.6 5437.6,2825 U29.1@5350,2825 5350,2615 U14.8@5365,2600 ; 5365,2075 5370,2070 5704.4,2070 U10.1@5772,2137.6 5857.6,2137.6 ; 5365,2075 5365,2110 U8.1@5350,2125 5315,2125 5300,2140 5300,2585 5315,2600 U14.8@5365,2600
  other v2: 5990,2125
"ISO +3.75V": C35.2 C40.1 J5.2 U12.8 U19.7 U21.1 U21.2 | length 3449.2
  Top Layer w10: U21.2@5625,1725 U21.1@5675,1725 v2(5745,1725) ; v1(5955,1610) 5955,1525.28 5954.72,1525 v1(5995,1525) ; v1(6195,1050) 6200,1045 C40.1@6200,969.09 ; v1(6590,1615) 6590,2270 6435.43,2424.57 C35.2@6435.43,2475 U19.7@6535,2475 6590,2475 v1(6600,2485)
  Signal Layer 1 w10: v1(5955,1610) 6000,1610 6045,1565 6215,1565 6265,1615 v1(6590,1615)
  Bottom Layer w10: v2(5745,1725) 5880,1725 5955,1650 v1(5955,1610) ; v1(5995,1525) 6085,1435 6085,1160 v1(6195,1050) ; J5.2@6575,2900 6640,2900 6650,2890 6650,2535 v1(6600,2485) v1@6610,2485
"ISO +5V": C16.1 C19.1 C27.2 D1.2 D4.2 JU1.2 JU4.2 R4.1 R5.1 R6.2 R10.2 U21.8 U22.8 | length 5045.1
  Top Layer w10: R10.2@5662.4,1400 5662.4,1442.4 5670,1450 v1(5670,1455) ; v1@5675,1455 U21.8@5675,1520.28 ; R4.1@6025,1212.4 v1(6025,1262.5) R5.1@6025,1312.6 6092.6,1312.6 6225,1445 U22.8@6225,1520.28 6270.28,1520.28 v1(6275,1525) ; R6.2@6125,3462.4 6317.6,3462.4 v1(6320,3460)
  Top Layer w12: C19.1@5569.09,500 C19.1@5600,530.91 ; D1.2@5788.58,975 5849.02,914.57 C27.2@5925,914.57 5989.57,914.57 6085,1010 6085,1190 6062.6,1212.4 R4.1@6025,1212.4
  Top Layer w20: JU4.2@5300,500 C19.1@5569.09,500 ; C19.1@5600,530.91 C16.1@5850,530.91 5850,688.58 D4.2@5788.58,750 D1.2@5788.58,975
  Bottom Layer w10: v1(5670,1455) 5862.5,1262.5 v1(6025,1262.5) ; v1(6275,1525) 6280,1530 6280,2535 6335,2590 6335,3445 v1(6320,3460)
  Bottom Layer w20: JU1.2@5300,300 JU4.2@5300,500
  other v2: 5850,635
"ISO -2.5V": C37.2 R12.2 U13.5 | length 2788.5
  Top Layer w10: C37.2@6450,1969.09 6500,1919.09 U13.5@6500,1779.72
  Top Layer w12: R12.2@5525,3237.4 5555,3267.4 v2(5555,3395) ; C37.2@6450,1969.09 v1(6450,2050)
  Signal Layer 1 w12: v1(5460,2130) 5540,2050 v1(6450,2050)
  Bottom Layer w12: v1(5460,2130) 5460,2980 5555,3075 v2(5555,3395)
"ISO -3.75V": C38.2 C39.2 J5.1 U12.5 U19.4 | length 2797.2
  Top Layer w10: v1(5755,1520) 5755.28,1520.28 U12.5@5800,1520.28 5800,1405.91 C38.2@5825,1380.91 ; J5.1@6575,2800 6725,2650 ; v1(6700,2625) 6725,2650 ; C39.2@6825,2589.57 6810.43,2575 U19.4@6750,2575 6750,2625 6725,2650
  Signal Layer 1 w10: v1(5755,1520) 5755,1495 5825,1425 6665,1425 v2(6670,1420)
  Bottom Layer w10: v2(6670,1420) 6670,2520 6690,2540 6690,2615 v1(6700,2625)
ISO_24_RESET: R40.1 U17.3 U28.4 | length 1690.6
  Top Layer w10: U28.4@5430,3500 5810,3500 5860,3550 v1(6225,3550) ; v1(6195,2925) 6195,2854.8 6200,2849.8 6312.6,2849.8 6312.6,2841 6321.4,2841 R40.1@6325,2837.4
  Bottom Layer w10: v1(6195,2925) 6255,2985 6255,3250 6240,3265 6240,3535 v1(6225,3550)
ISO_BAT_VOLT: C34.2 R6.1 R27.2 U3.14 | length 332.7
  Top Layer w10: U3.14@5925,3257.68 C34.2@5925,3389.57 6023.03,3389.57 R27.2@6025,3387.6 R6.1@6125,3387.6
ISO_DRDY: U3.25 U29.2 | length 531.9
  Top Layer w10: v1(5290,2875) U29.2@5350,2875 ; v1(5640,2970) 5640,2975 5666.77,3001.77 U3.25@5706.5,3001.77
  Signal Layer 1 w10: v1(5290,2875) 5545,2875 v1(5640,2970)
ISO_FSS: R41.1 U3.24 U14.6 | length 927.3
  Top Layer w10: U14.6@5365,2500 5462.4,2500 R41.1@5475,2512.6 5532.6,2512.6 v1(5570,2550) ; U3.24@5706.5,3027.36 5747.64,3027.36 5755,3020 v1(5795,3020)
  Bottom Layer w10: v1(5570,2550) 5570,2875 5620,2925 5650,2925 5745,3020 v1(5795,3020)
ISO_GND: C1.1 C12.1 C16.2 C19.2 C26.2 C27.1 C29.2 C30.1 C32.1 C33.1 C34.1 C35.1 C37.1 C38.1 C39.1 C40.2 C46.1 C47.2 C48.2 C49.1 J5.3 J5.4 J6.2 JU5.2 Q1.2 R27.1 T1.5 TP1.1 U1.3 U2.3 U3.2 U3.3 U3.7 U3.8 U3.10 U3.15 U6.5 U8.4 U10.2 U11.5 U12.3 U12.6 U13.3 U13.6 U14.5 U17.2 U21.3 U21.6 U21.7 U22.3 U22.6 U22.7 U28.3 U29.4 | length 3876.6
  Top Layer w10: U8.4@5350,2275 v1(5350,2305) ; v1(5350,3010) U29.4@5350,2975 U29.4@5365,2975 ; v1(5365,1770) U11.5@5365,1800 ; U14.5@5365,2450 5420,2450 v1(5430,2440) ; U6.5@5391,1475 U6.5@5365,1475 5425,1475 v1(5430,1470) ; v1(5430,1170) U1.3@5430,1225 ; v1(5430,3065) U2.3@5430,3125 5430,3087 ; v1(5430,3352) U28.3@5430,3400 ; v1(5535,1165) Q1.2@5535,1210.2 ; v1(5570,2965) 5600,2995 C32.1@5600,3014.57 ; U21.6@5575,1520.28 5575,1610 v1(5595,1630) ; U21.3@5575,1725 5575,1650 v1(5595,1630) ; C19.2@5600,269.09 C19.2@5643,269.09 ; C33.1@5600,3235.43 v1(5650,3285.43) ; U21.7@5625,1520.28 5625,1600 v1(5595,1630) ; v1(5635,2360) 5635.43,2360.43 C12.1@5675,2360.43 ; U3.15@5706.5,3257.68 5677.76,3257.68 v1(5650,3285.43) ; U10.2@5772,2175 v1(5825,2175) ; C38.1@5825,1119.09 5855.91,1119.09 v1(5895,1080) ; 5850,1591 U12.6@5850,1520.28 v1(5850,1620) U12.3@5850,1725 ; v1(5855,3155) 5855.31,3155.31 U3.10@5925,3155.31 ; C27.1@5925,985.43 5925,975 v1(5975,1025) ; U3.2@5925,2950.59 5984.41,2950.59 5958.82,2976.18 U3.3@5925,2976.18 ; U3.7@5925,3078.54 5986.46,3078.54 ; U3.8@5925,3104.13 5980.87,3104.13 v1(6000,3085) ; v1@5970,2535 5975,2530 C47.2@5975,2480.91 ; C26.2@5985.43,2825 5985.43,2860.43 v1(5990,2865) ; v1(6000,3300) 6039.57,3300 C46.1@6050,3310.43 ; R27.1@6032,3462.4 R27.1@6027.4,3462.4 ; v1(6057,3024) C1.1@6057,3057.57 ; v1(6065,3500) R27.1@6027.4,3462.4 ; v1(6100,2560) C30.1@6100,2614.57 ; U22.6@6125,1520.28 U22.7@6175,1520.28 ; U22.3@6125,1725 6125,1650 v1(6150,1625) 6175,1600 U22.7@6175,1520.28 ; v1(6150,3025) C48.2@6150,3064.57 ; C49.1@6150,3285.43 6164.57,3300 v1(6200,3300) ; U22.7@6168.75,1546.46 U22.7@6175,1520.28 ; v1(6195,1290) 6200,1285 C40.2@6200,1230.91 ; U17.2@6197.6,2815 v1(6255,2815) v1@6252.4,2812.4 ; C29.2@6200,2180.91 6200,2215 v1(6200,2240) ; v1(6315,2475) C35.1@6364.57,2475 ; C37.1@6407,2230.91 C37.1@6450,2230.91 v1(6450,2290) ; U13.3@6450,1575 v1(6450,1690) U13.6@6450,1779.72 ; 6825,2688 C39.1@6825,2660.43 v1(6825,2715) ; v1(5650,3285.43) 5825,3460.43 C34.1@5925,3460.43 6023.03,3460.43 6023.03,3462.4 R27.1@6025,3462.4 R27.1@6027.4,3462.4
  Top Layer w20: v1(5605,205) C19.2@5605,264.1 ; v1(5850,205) C16.2@5850,269.09
  other v1: 5975,2540 5985,2950
ISO_PWR_ON: Q1.1 R4.2 U1.4 | length 719.4
  Top Layer w10: U1.4@5430,1325 5581.89,1325 5587.4,1319.49 ; Q1.1@5535,1285 5535,1325 ; 5587.91,1320 v1(5675,1320) ; v1(5935,1190) 5935,1195 5992.4,1137.6 R4.2@6025,1137.6
  Bottom Layer w10: v1(5675,1320) 5805,1190 v1(5935,1190)
ISO_SCLK: R17.1 U6.6 | length 1522.4
  Top Layer w10: U6.6@5365,1525 5415,1525 5445,1555 v1(5445,1685) ; R17.1@5700,2793.5 5700,2785 v1(5740,2745)
  Bottom Layer w10: v1(5445,1685) 5445,1770 5530,1855 5620,1855 5710,1945 5710,2715 v1(5740,2745)
ISO_SDI: U3.27 U11.6 | length 1479.9
  Top Layer w10: U11.6@5365,1850 5420,1850 5440,1870 v1(5440,1925) ; U3.27@5706.5,2950.59 5784.41,2950.59 v1(5790,2945)
  Bottom Layer w10: v1(5440,1925) 5595,1925 5665,1995 5665,2820 v1(5790,2945)
ISO_SDO: U3.26 U8.2 | length 1102.1
  Top Layer w10: U8.2@5350,2175 5425,2175 5455,2205 5455,2300 v1(5585,2430) ; U3.26@5706.5,2976.18 5766.18,2976.18 v1(5775,2985)
  Bottom Layer w10: v1(5585,2430) 5585,2435 5620,2470 5620,2830 v1(5775,2985)
ISO_START: R18.1 U2.4 U3.23 | length 818.6
  Top Layer w10: U2.4@5430,3225 5375,3170 5375,3055 v1(5430,3000) 5450,2980 R18.1@5450,2887.4 ; U3.23@5706.5,3052.95 5767.95,3052.95 v1(5770,3055)
  Signal Layer 1 w10: v1@5435,3000 5477.7,3042.7 5757.7,3042.7 v1(5770,3055)
  Bottom Layer w10: v1(5430,3000) v1@5435,3000
M0PWM0: J22.19 U31.131 | length 897.5
  Top Layer w10: U31.131@1025.76,1611.42 1071.42,1611.42 1095,1635 1095,1640 v1(1090,1645)
  Signal Layer 1 w10: J22.19@325,1725 335,1735 865,1735 955,1645 v1(1090,1645)
M0PWM1: J22.20 U31.132 | length 1034.4
  Top Layer w10: U31.132@1025.76,1591.73 1091.73,1591.73 v1(1115,1615)
  Signal Layer 1 w10: J22.20@225,1725 275,1675 782,1675 785,1672 858,1672 915,1615 v1(1115,1615)
NetC1_2: C1.2 U3.9 | length 130.7
  Top Layer w10: U3.9@5925,3129.72 6044.29,3129.72 6044.29,3135.43 C1.2@6050,3135.43
NetC2_2: C2.2 U7.9 | length 108.4
  Top Layer w10: U7.9@4561,2213.39 4652.95,2213.39 C2.2@4664.57,2225
NetC3_1: C3.1 R9.3 U4.2 U4.6 | length 501.1
  Top Layer w10: R9.3@4440,700 4440,795.43 C3.1@4435.43,800 4435.43,805.43 4480,850 4575,850 ; U4.6@4575,785 4575,850 ; U4.2@4625,1000 4625,930 4575,880 4575,850
NetC12_2: C12.2 U10.4 | length 78.4
  Top Layer w10: C12.2@5675,2289.57 5675,2215.4 U10.4@5678,2212.4
NetC13_2: C13.2 U24.4 | length 67.4
  Top Layer w10: U24.4@4287.4,3072 4338.43,3072 C13.2@4350,3060.43
NetC17_1: C17.1 U20.3 | length 301.1
  Top Layer w12: U20.3@3600,1600 3665,1600 3680,1615 3680,1775 3655,1800 C17.1@3635.43,1800
NetC18_1: C18.1 U20.7 | length 145.6
  Top Layer w12: C18.1@3485.43,1325 3560.43,1400 U20.7@3600,1400
NetC20_1: C20.1 U20.2 | length 129.3
  Top Layer w12: C20.1@3475,1660.43 3485.43,1650 U20.2@3600,1650
NetC20_2: C20.2 U20.4 | length 141.4
  Top Layer w12: C20.2@3475,1589.57 3514.57,1550 U20.4@3600,1550
NetC21_1: C21.1 U20.5 | length 129.3
  Top Layer w12: C21.1@3475,1510.43 3485.43,1500 U20.5@3600,1500
NetC21_2: C21.2 U20.6 | length 129.3
  Top Layer w12: C21.2@3475,1439.57 3485.43,1450 U20.6@3600,1450
NetC23_1: C23.1 U23.5 | length 104.3
  Top Layer w10: C23.1@4200,1510.43 4210.43,1500 U23.5@4300,1500
NetC23_2: C23.2 U23.6 | length 104.3
  Top Layer w10: C23.2@4200,1439.57 4210.43,1450 U23.6@4300,1450
NetC26_1: C26.1 R2.1 U3.1 | length 180.1
  Top Layer w10: R2.1@5912.6,2750 5912.6,2823.03 C26.1@5914.57,2825 5925,2835.43 U3.1@5925,2925
NetC28_1: C28.1 R46.1 U7.1 | length 179.2
  Top Layer w10: U7.1@4561,2008.66 4623.66,2008.66 4630,2015 4662.6,2015 R46.1@4662.6,2090
NetC31_1: C31.1 U13.2 | length 241.3
  Top Layer w10: C31.1@6319.09,1400 6375,1400 6400,1425 U13.2@6400,1575
NetC31_2: C31.2 U13.4 | length 226.1
  Top Layer w10: U13.4@6500,1575 6530,1575 6580.91,1524.09 C31.2@6580.91,1400
NetC32_2: C32.2 R3.1 U3.22 | length 185.2
  Top Layer w10: R3.1@5525,3087.4 5598.03,3087.4 C32.2@5600,3085.43 5606.89,3078.54 U3.22@5706.5,3078.54
NetC33_2: C33.2 R12.1 U3.21 | length 212.9
  Top Layer w10: R12.1@5525,3162.6 5598.03,3162.6 C33.2@5600,3164.57 5600,3155 5650.87,3104.13 U3.21@5706.5,3104.13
